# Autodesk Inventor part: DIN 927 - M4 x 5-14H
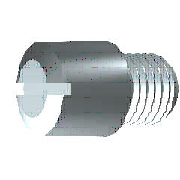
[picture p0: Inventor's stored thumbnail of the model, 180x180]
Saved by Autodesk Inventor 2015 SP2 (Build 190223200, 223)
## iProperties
Created: 2014-02
Part Number: DIN 927 - M4 x 5-14H
Material: Stahl, weich
Description: Passschraube kopflos
Document SubType Name: Modeling
Standard: DIN 927
Designer: rYan
Standards Organization: DIN
Language: de-DE
Size Designation: M4 x 5-14H
Categories: <MemberInstance><Categories><Category DisplayName="Verbindungselemente" InternalName="e4da775c-781d-43d5-af7c-5136215cf5a6" Mnemonic="FSTN"><Category DisplayNam
Density: 7.85 g/cm^3
Appearance: Halbpoliert
IsCustomPart: 0
Author: rYan
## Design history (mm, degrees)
body "Solid1"
sketch "Skizze1"
  geometry: L1 (0, 0)-(11, 0); L2 (11, 0)-(11, 2); L3 (11, 2)-(5, 2); L4 (5, 2)-(5, 2.75); L5 (5, 2.75)-(0, 2.75); L6 (0, 2.75)-(0, 0); L7 (-2.2, 0)-(13.2, 0) reference; L8 (0, -0.55)-(0, 3.3) reference; A1 r 0.6 centre (5.3, 2.52) between (5, 2) and (5.6, 2)
  constraints: 12 end point, 4 parallel, 2 collinear, 2 point on circle, 1 centre point, 1 horizontal, 1 perpendicular, 1 point on line
  dimensions: "d0" = 5 distance between parallel lines of L4 L6 (= KOH); "d1" = 6 distance between parallel lines of L2 L4 (= GEL); "d2" = 4 diameter of L3 L1 (= NND); "d3" = 5.5 diameter of L5 L1 (= KOD); "d14" = 0.6 distance of A1.end L3.end (= SBR); "d15" = 0.6 radius of A1 (= SBR)
revolve "Körper" stored, may be unused: angle "d4" = 90 deg
sketch "Skizze2"
  geometry: L1 (0, -3.85)-(0, 3.85) reference; L2 (-3.85, 0)-(3.85, 0) reference; L3 (-2.75, 0.3)-(2.75, 0.3); L4 (2.75, 0.3)-(2.75, -0.3); L5 (2.75, -0.3)-(-2.75, -0.3); L6 (-2.75, -0.3)-(-2.75, 0.3); L7 (-2.75, 0)-(2.75, 0); L8 (0, 0.3)-(0, -0.3); C1 r 2.75 at (0, 0) reference
  constraints: 12 end point, 4 midpoint, 2 collinear, 2 parallel, 1 horizontal, 1 perpendicular, 1 tangent
  dimensions: "d5" = 0.6 distance between parallel lines of L3 L5 (= SBR)
extrude "Loch" cut sketch "Skizze2" distance "d6" = 1.12 (= STI); taper "d7" = 0 deg
chamfer "Fase1" distance "d8" = 0.8 (= PHH); stored, may be unused: angle "d9" = 45 deg, second distance "d19" = 0.8 (= PHH)
feature "Gewinde" dims "d10" = 6 (= GEL), "d11" = 0
chamfer "Fase2" distance "d12" = 0.42941 (= -0.5 x GD1 + 0.5 x NND); stored, may be unused: second distance "d13" = 0.42941 (= GUL), angle "d20" = 45 deg
revolve "Nut1" stored, may be unused: angle "d16" = 90 deg
workplane "Work Plane1"
other parameters: "NND" = 4 [user parameter; used in 2 equation terms], "GEL" = 6 [user parameter; used in 3 equation terms], "KOD" = 5.5 [user parameter; used in 1 equation term], "KOH" = 5 [user parameter; used in 1 equation term], "SBR" = 0.6 [user parameter; used in 3 equation terms], "GUL" = 0.42941 (= 0.61345 x PTC) [user parameter; used in 1 equation term], "PHH" = 0.8 [user parameter; used in 2 equation terms], "GD1" = 3.14117 (= THREADDIA - 1.2269 x PTC) [user parameter; used in 1 equation term], "STI" = 1.12 [user parameter; used in 1 equation term], "d18" = 0, "d21" = 0, "d23" = 0, "THREADDIA" = 4 [user parameter; used in 1 equation term], "TOA" = 30 deg [user parameter], "NLG" = 6 (= GEL) [user parameter], "TPU" = 14.28571 (computed from PTC) [user parameter], "PTC" = 0.7 [user parameter; used in 4 equation terms], "GAL" = 0.42941 (= 0.61345 x PTC) [user parameter]
